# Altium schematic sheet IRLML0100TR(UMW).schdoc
size 127 x 101 mm
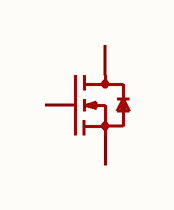
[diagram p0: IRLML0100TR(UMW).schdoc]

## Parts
Q?  irlml0100tr(umw)  [SOT-23-3_L2.9-W1.3-P1.90-LS2.4-BR]  (value not drawn)

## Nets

Not connected (* = marked no-connect by the designer): Q? 1(G) 2(S) 3(D)

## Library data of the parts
Q? = irlml0100tr(umw): 数量:-;漏源电压(Vdss):100V;连续漏极电流(Id):1.6A;导通电阻(RDS(on)):220mΩ@10V,1.6A;耗散功率(Pd):1.3W;阈值电压(Vgs(th)):2.5V;; Manufacturer: UMW(友台半导体); AddInBom: yes; ModelId: c62791f0466c4ae2a892c056b845b0ca; ModelName: SOT-23-3P_L2.9-W1.3-H1.0-LS2.4-P0.95; ModelTransform: 98.425,114.173,0,180,0,0,0.0005,-0.0005,0; Drain to Source Voltage: 100V; Pd - Power Dissipation: 1.3W; Gate Threshold Voltage (Vgs(th)): 2.5V; Gate Charge(Qg): 2.5nC; Input Capacitance(Ciss): 290pF; Reverse Transfer Capacitance (Crss@Vds): 13pF; Output Capacitance(Coss): 27pF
